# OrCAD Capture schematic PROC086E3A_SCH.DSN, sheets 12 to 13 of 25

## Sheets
12 14. CODEC-B STEREO_MIC 2: size C; title: CODEC-B STEREO MIC 2
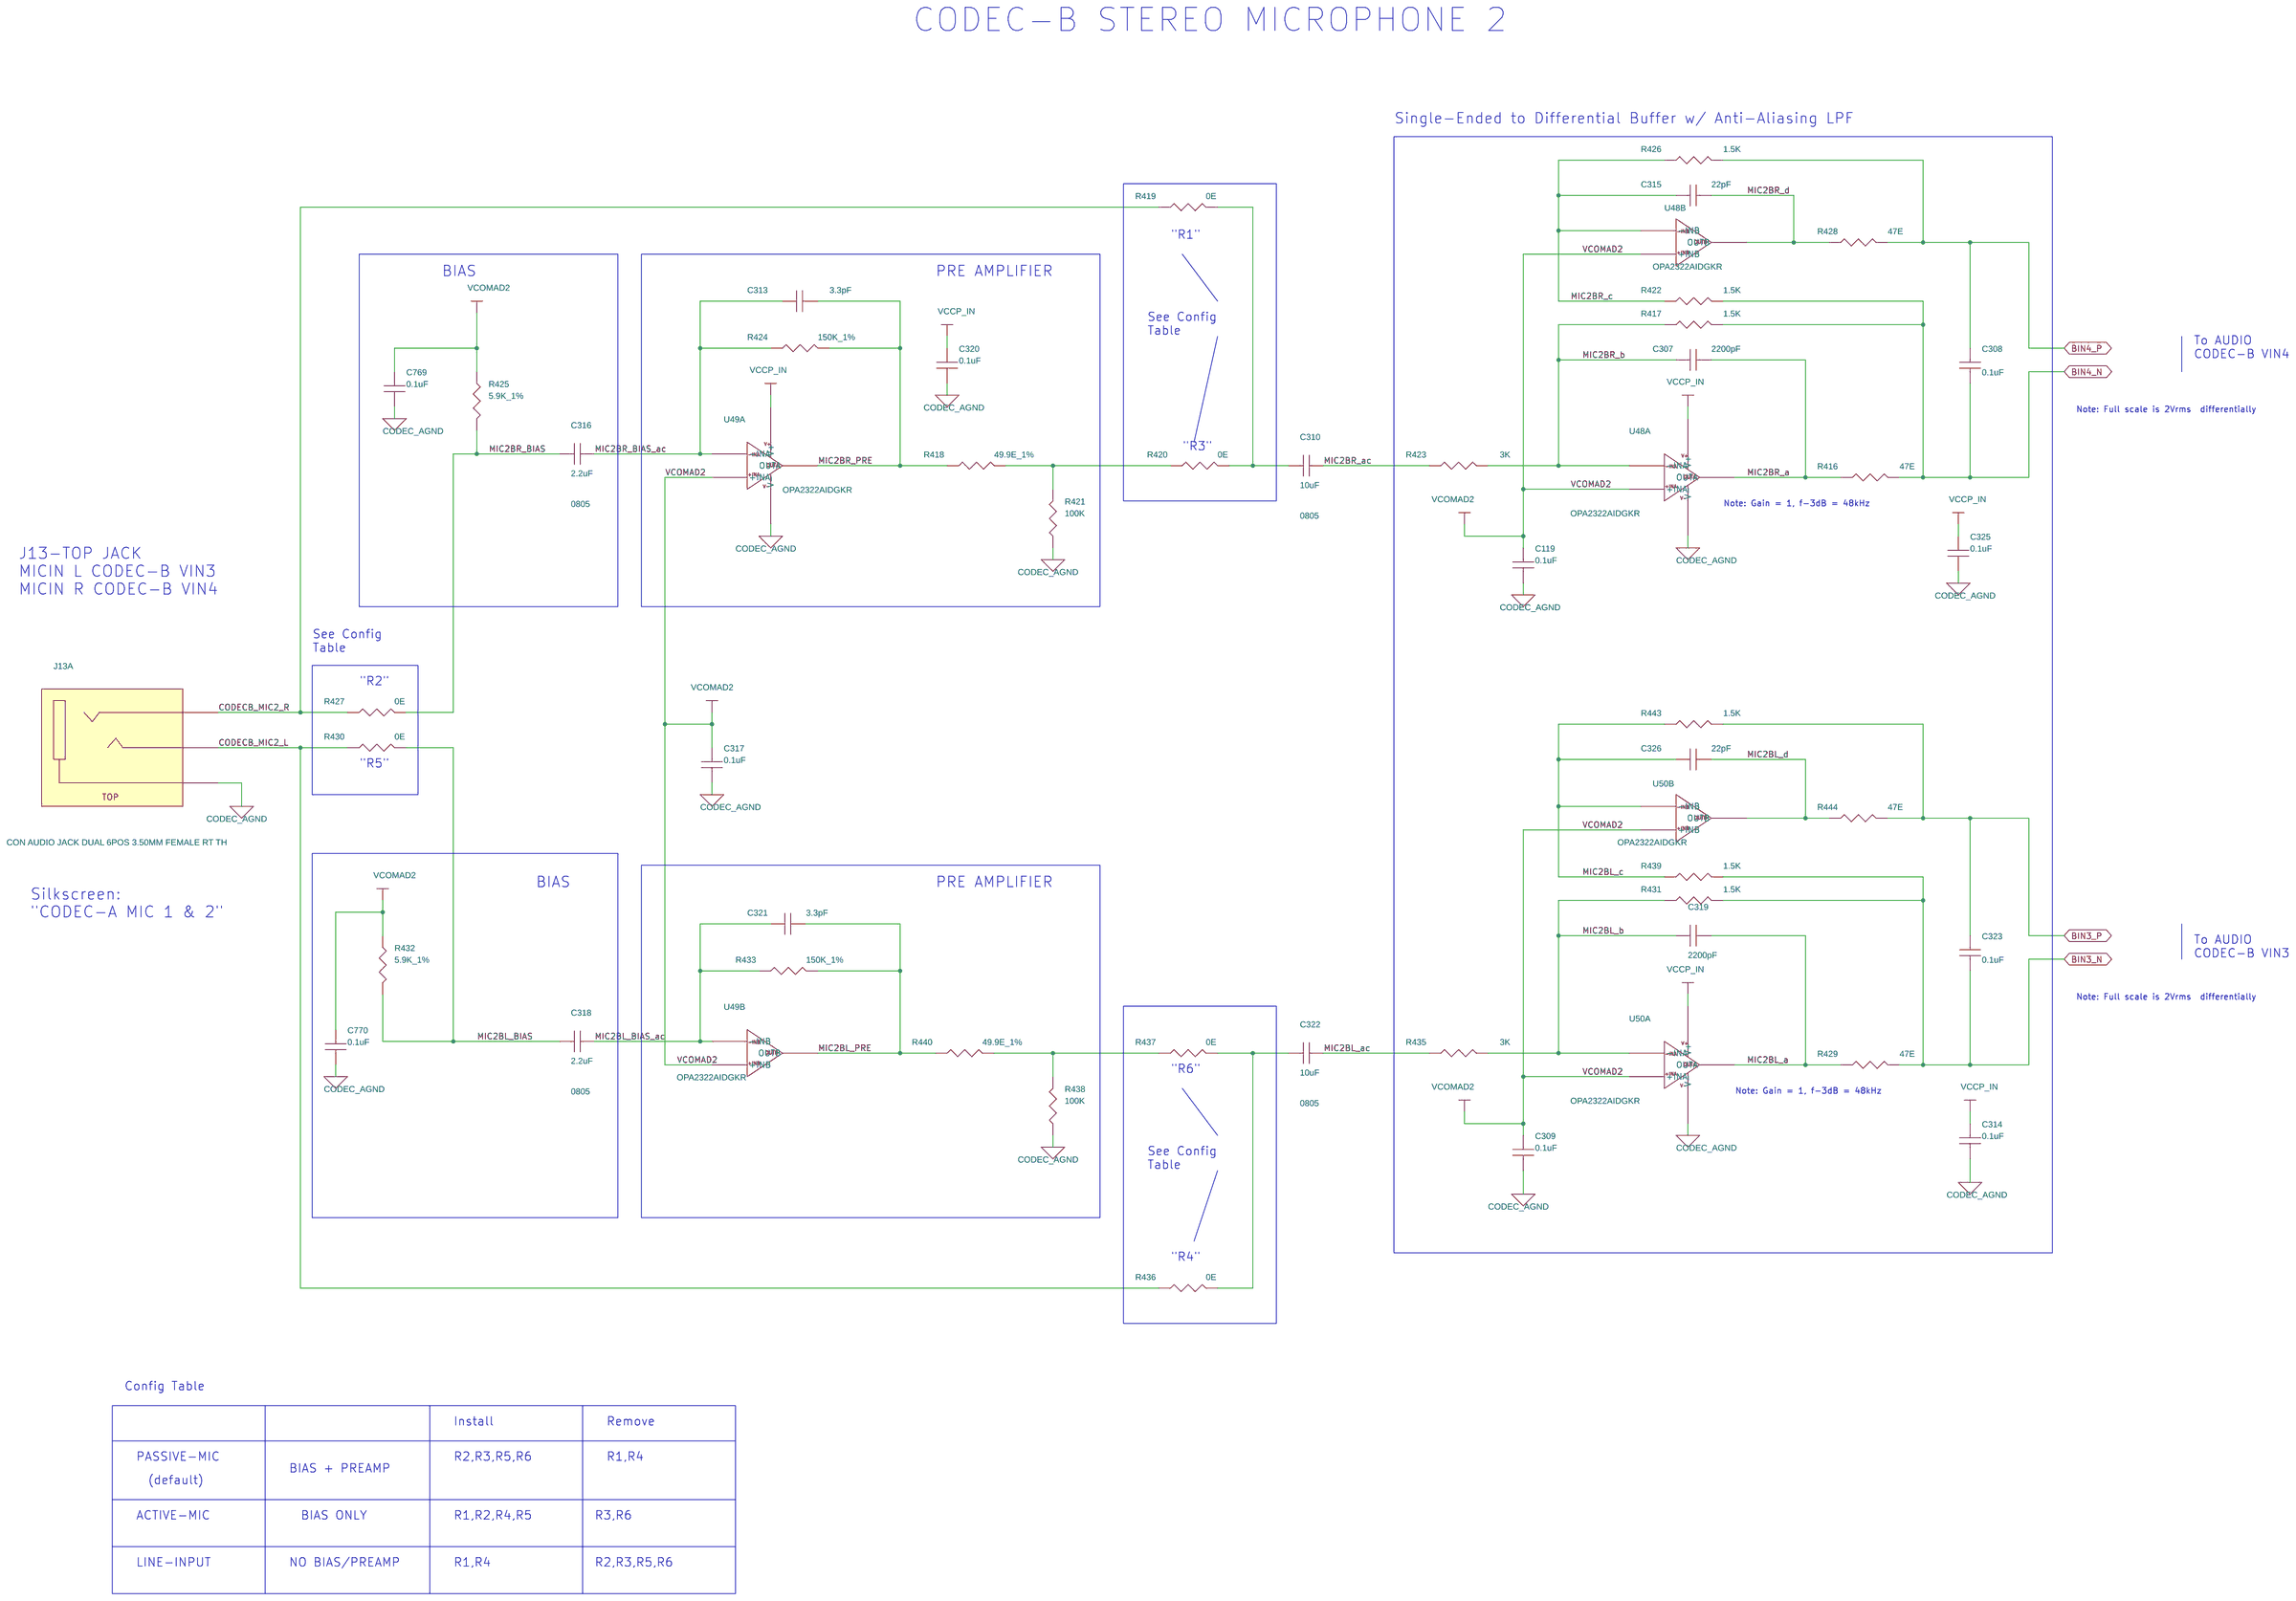
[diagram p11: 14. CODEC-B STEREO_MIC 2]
13 15. CODEC-B STEREO_LINE_OUT: size C; title: CODEC-B STEREO LINE OUT
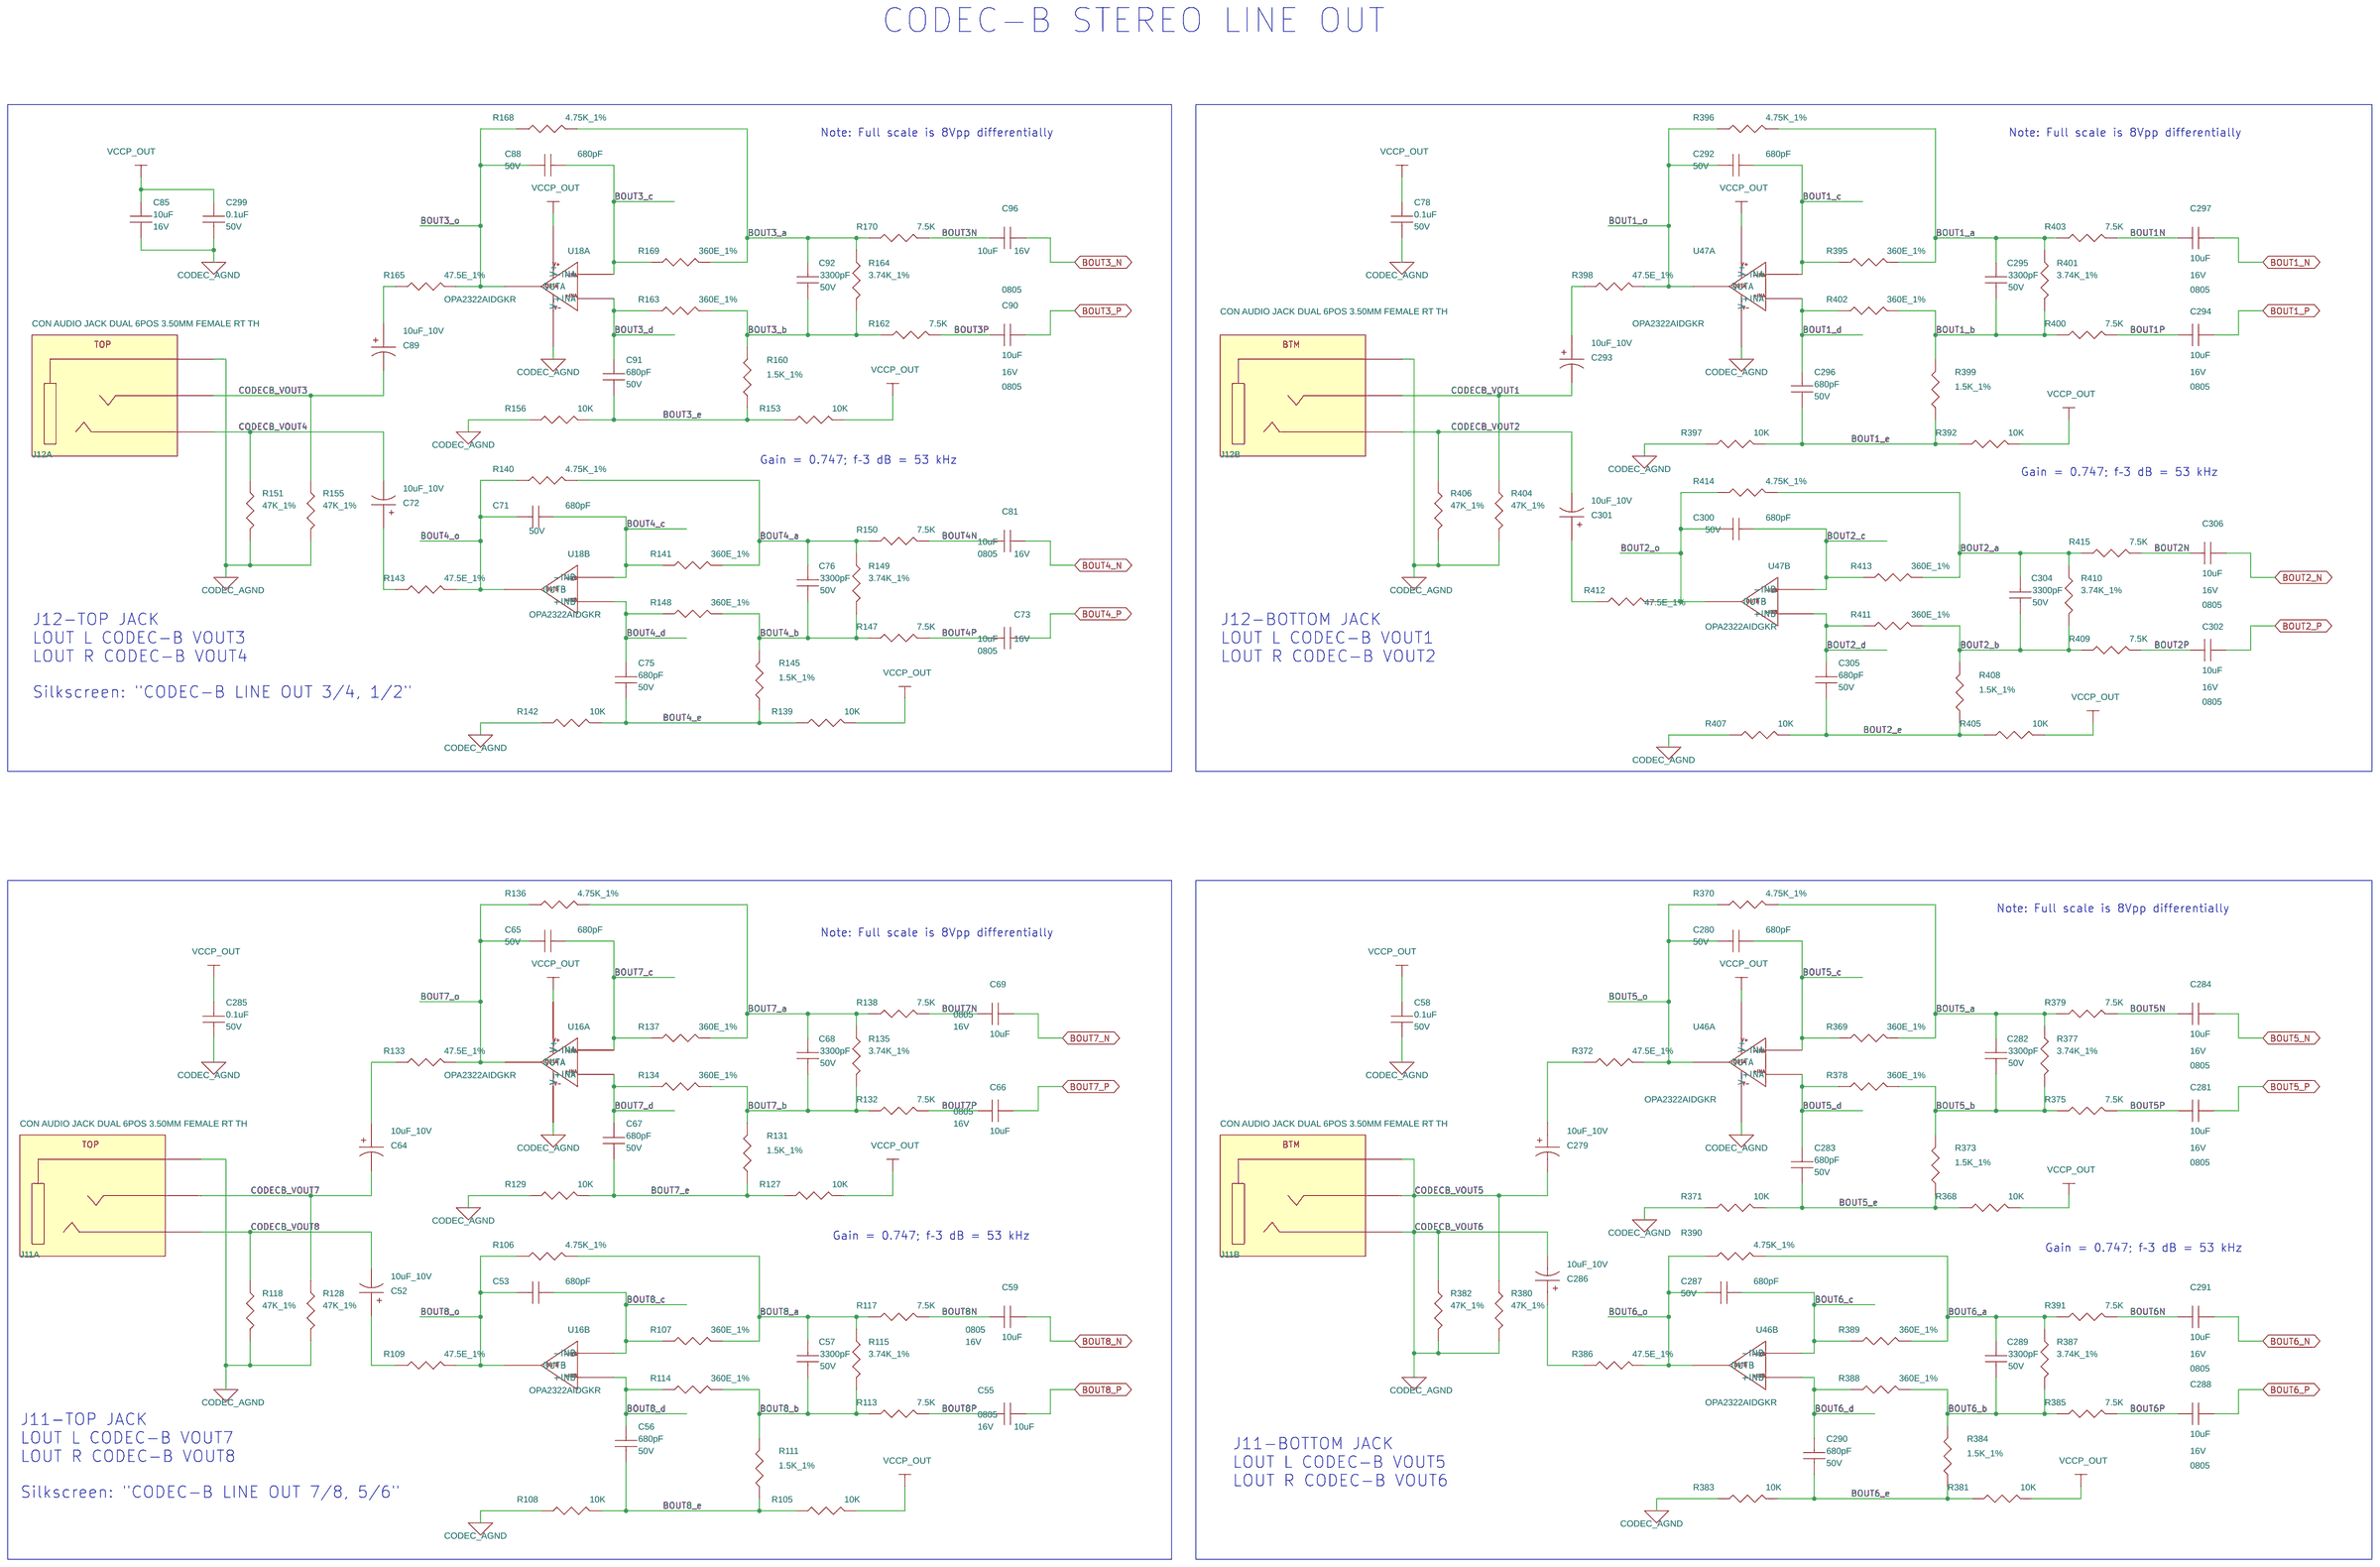
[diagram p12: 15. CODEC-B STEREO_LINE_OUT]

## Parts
sheet 13. CODEC-B STEREO_MIC 1
J13  CON_AUDIOJACK6_STX-4235  [CON_AV6_STX-4235-3-3_S_R_T_26]  (sections A,B)
sheet 14. CODEC-B STEREO_MIC 2
C119  0.1uF  [CAP0402_0-75]
C307  2200pF  [CAP0402_0-75]
C308  0.1uF  [CAP0402_0-75]
C309  0.1uF  [CAP0402_0-75]
C310  10uF  [CAP0805_1-5]
C313  3.3pF  [CAP0402_0-75]
C314  0.1uF  [CAP0402_0-75]
C315  22pF  [CAP0402_0-75]
C316  2.2uF  [CAP0805_1-5]
C317  0.1uF  [CAP0402_0-75]
C318  2.2uF  [CAP0805_1-5]
C319  2200pF  [CAP0402_0-75]
C320  0.1uF  [CAP0402_0-75]
C321  3.3pF  [CAP0402_0-75]
C322  10uF  [CAP0805_1-5]
C323  0.1uF  [CAP0402_0-75]
C325  0.1uF  [CAP0402_0-75]
C326  22pF  [CAP0402_0-75]
C769  0.1uF  [CAP0402_0-75]
C770  0.1uF  [CAP0402_0-75]
R416  47E  [RES0402_0-5]
R417  1.5K  [RES0402_0-5]
R418  49.9E_1%  [RES0402_0-5]
R419  0E  [RES0402_0-5]
R420  0E  [RES0402_0-5]
R421  100K  [RES0402_0-5]
R422  1.5K  [RES0402_0-5]
R423  3K  [RES0402_0-5]
R424  150K_1%  [RES0402_0-5]
R425  5.9K_1%  [RES0402_0-5]
R426  1.5K  [RES0402_0-5]
R427  0E  [RES0402_0-5]
R428  47E  [RES0402_0-5]
R429  47E  [RES0402_0-5]
R430  0E  [RES0402_0-5]
R431  1.5K  [RES0402_0-5]
R432  5.9K_1%  [RES0402_0-5]
R433  150K_1%  [RES0402_0-5]
R435  3K  [RES0402_0-5]
R436  0E  [RES0402_0-5]
R437  0E  [RES0402_0-5]
R438  100K  [RES0402_0-5]
R439  1.5K  [RES0402_0-5]
R440  49.9E_1%  [RES0402_0-5]
R443  1.5K  [RES0402_0-5]
R444  47E  [RES0402_0-5]
U48  OPA2322AIDGKR  [VSSOP8_25-59_120X120_1-1]  (sections A,B)
U49  OPA2322AIDGKR  [VSSOP8_25-59_120X120_1-1]  (sections A,B)
U50  OPA2322AIDGKR  [VSSOP8_25-59_120X120_1-1]  (sections A,B)
sheet 15. CODEC-B STEREO_LINE_OUT
C52  10uF_10V  [CAPCT0805H_1]
C53  680pF  [CAP0402_0-75]
C55  10uF  [CAP0805_1-5]
C56  680pF  [CAP0402_0-75]
C57  3300pF  [CAP0402_0-75]
C58  0.1uF  [CAP0402_0-75]
C59  10uF  [CAP0805_1-5]
C64  10uF_10V  [CAPCT0805H_1]
C65  680pF  [CAP0402_0-75]
C66  10uF  [CAP0805_1-5]
C67  680pF  [CAP0402_0-75]
C68  3300pF  [CAP0402_0-75]
C69  10uF  [CAP0805_1-5]
C71  680pF  [CAP0402_0-75]
C72  10uF_10V  [CAPCT0805H_1]
C73  10uF  [CAP0805_1-5]
C75  680pF  [CAP0402_0-75]
C76  3300pF  [CAP0402_0-75]
C78  0.1uF  [CAP0402_0-75]
C81  10uF  [CAP0805_1-5]
C85  10uF  [CAP0603_1]
C88  680pF  [CAP0402_0-75]
C89  10uF_10V  [CAPCT0805H_1]
C90  10uF  [CAP0805_1-5]
C91  680pF  [CAP0402_0-75]
C92  3300pF  [CAP0402_0-75]
C96  10uF  [CAP0805_1-5]
C279  10uF_10V  [CAPCT0805H_1]
C280  680pF  [CAP0402_0-75]
C281  10uF  [CAP0805_1-5]
C282  3300pF  [CAP0402_0-75]
C283  680pF  [CAP0402_0-75]
C284  10uF  [CAP0805_1-5]
C285  0.1uF  [CAP0402_0-75]
C286  10uF_10V  [CAPCT0805H_1]
C287  680pF  [CAP0402_0-75]
C288  10uF  [CAP0805_1-5]
C289  3300pF  [CAP0402_0-75]
C290  680pF  [CAP0402_0-75]
C291  10uF  [CAP0805_1-5]
C292  680pF  [CAP0402_0-75]
C293  10uF_10V  [CAPCT0805H_1]
C294  10uF  [CAP0805_1-5]
C295  3300pF  [CAP0402_0-75]
C296  680pF  [CAP0402_0-75]
C297  10uF  [CAP0805_1-5]
C299  0.1uF  [CAP0402_0-75]
C300  680pF  [CAP0402_0-75]
C301  10uF_10V  [CAPCT0805H_1]
C302  10uF  [CAP0805_1-5]
C304  3300pF  [CAP0402_0-75]
C305  680pF  [CAP0402_0-75]
C306  10uF  [CAP0805_1-5]
J11  CON_AUDIOJACK6_STX-4235  [CON_AV6_STX-4235-3-3_S_R_T_26]  (sections A,B)
J12  CON_AUDIOJACK6_STX-4235  [CON_AV6_STX-4235-3-3_S_R_T_26]  (sections A,B)
R105  10K  [RES0402_0-5]
R106  4.75K_1%  [RES0402_0-5]
R107  360E_1%  [RES0402_0-5]
R108  10K  [RES0402_0-5]
R109  47.5E_1%  [RES0402_0-5]
R111  1.5K_1%  [RES0402_0-5]
R113  7.5K  [RES0402_0-5]
R114  360E_1%  [RES0402_0-5]
R115  3.74K_1%  [RES0402_0-5]
R117  7.5K  [RES0402_0-5]
R118  47K_1%  [RES0402_0-5]
R127  10K  [RES0402_0-5]
R128  47K_1%  [RES0402_0-5]
R129  10K  [RES0402_0-5]
R131  1.5K_1%  [RES0402_0-5]
R132  7.5K  [RES0402_0-5]
R133  47.5E_1%  [RES0402_0-5]
R134  360E_1%  [RES0402_0-5]
R135  3.74K_1%  [RES0402_0-5]
R136  4.75K_1%  [RES0402_0-5]
R137  360E_1%  [RES0402_0-5]
R138  7.5K  [RES0402_0-5]
R139  10K  [RES0402_0-5]
R140  4.75K_1%  [RES0402_0-5]
R141  360E_1%  [RES0402_0-5]
R142  10K  [RES0402_0-5]
R143  47.5E_1%  [RES0402_0-5]
R145  1.5K_1%  [RES0402_0-5]
R147  7.5K  [RES0402_0-5]
R148  360E_1%  [RES0402_0-5]
R149  3.74K_1%  [RES0402_0-5]
R150  7.5K  [RES0402_0-5]
R151  47K_1%  [RES0402_0-5]
R153  10K  [RES0402_0-5]
R155  47K_1%  [RES0402_0-5]
R156  10K  [RES0402_0-5]
R160  1.5K_1%  [RES0402_0-5]
R162  7.5K  [RES0402_0-5]
R163  360E_1%  [RES0402_0-5]
R164  3.74K_1%  [RES0402_0-5]
R165  47.5E_1%  [RES0402_0-5]
R168  4.75K_1%  [RES0402_0-5]
R169  360E_1%  [RES0402_0-5]
R170  7.5K  [RES0402_0-5]
R368  10K  [RES0402_0-5]
R369  360E_1%  [RES0402_0-5]
R370  4.75K_1%  [RES0402_0-5]
R371  10K  [RES0402_0-5]
R372  47.5E_1%  [RES0402_0-5]
R373  1.5K_1%  [RES0402_0-5]
R375  7.5K  [RES0402_0-5]
R377  3.74K_1%  [RES0402_0-5]
R378  360E_1%  [RES0402_0-5]
R379  7.5K  [RES0402_0-5]
R380  47K_1%  [RES0402_0-5]
R381  10K  [RES0402_0-5]
R382  47K_1%  [RES0402_0-5]
R383  10K  [RES0402_0-5]
R384  1.5K_1%  [RES0402_0-5]
R385  7.5K  [RES0402_0-5]
R386  47.5E_1%  [RES0402_0-5]
R387  3.74K_1%  [RES0402_0-5]
R388  360E_1%  [RES0402_0-5]
R389  360E_1%  [RES0402_0-5]
R390  4.75K_1%  [RES0402_0-5]
R391  7.5K  [RES0402_0-5]
R392  10K  [RES0402_0-5]
R395  360E_1%  [RES0402_0-5]
R396  4.75K_1%  [RES0402_0-5]
R397  10K  [RES0402_0-5]
R398  47.5E_1%  [RES0402_0-5]
R399  1.5K_1%  [RES0402_0-5]
R400  7.5K  [RES0402_0-5]
R401  3.74K_1%  [RES0402_0-5]
R402  360E_1%  [RES0402_0-5]
R403  7.5K  [RES0402_0-5]
R404  47K_1%  [RES0402_0-5]
R405  10K  [RES0402_0-5]
R406  47K_1%  [RES0402_0-5]
R407  10K  [RES0402_0-5]
R408  1.5K_1%  [RES0402_0-5]
R409  7.5K  [RES0402_0-5]
R410  3.74K_1%  [RES0402_0-5]
R411  360E_1%  [RES0402_0-5]
R412  47.5E_1%  [RES0402_0-5]
R413  360E_1%  [RES0402_0-5]
R414  4.75K_1%  [RES0402_0-5]
R415  7.5K  [RES0402_0-5]
U16  OPA2322AIDGKR  [VSSOP8_25-59_120X120_1-1]  (sections A,B)
U18  OPA2322AIDGKR  [VSSOP8_25-59_120X120_1-1]  (sections A,B)
U46  OPA2322AIDGKR  [VSSOP8_25-59_120X120_1-1]  (sections A,B)
U47  OPA2322AIDGKR  [VSSOP8_25-59_120X120_1-1]  (sections A,B)

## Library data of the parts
J11-J13 = CON_AUDIOJACK6_STX-4235-3_3: CON AUDIO JACK DUAL 6POS 3.50MM FEMALE RT TH; Chkd/date: MANIRAJA/090818; Crtd /date: ALVY/080818; Custom_Duty: 24%; Customs_HS_Code: 85369090; Distributor_name: MOUSER; Distributor_part_number: 806-STX-4235-3/3-N; Footprint Path: Y:\MIS_DATABASE\Library\ALTIUM_TOOL\PCB_FOOTPRINTS\Altium_Footprint_Lib.PcbLib; Height: 26.00MM; Library Path: Y:\MIS_DATABASE\Library\ALTIUM_TOOL\SCHEMATICS_PARTS\MS_CONNECTOR_Library.schlib; Library Ref: CON_AUDIOJACK6_STX-4235-3/3; Mfr_name: KYCON; Mfr_part_number: STX-4235-3/3-N; Mistral Part No: 150018080005-R; Package: THRU-HOLE; Part_type: CONNECTOR\JACK; Project: TI_J7ES_EVM_FUSION2_SER_CAP; RoHS: RoHS; Temperature: -25°C+85°C; Tolerance: NA; Voltage: NA; Wattage: NA; Weight: NA; Datasheet: Y:\MIS_DATABASE\DATASHEETS\CONNECTORS\STX-4235-3-3-N.PDF
C58 C78 C119 C285 C299 C308 C309 C314 C317 C320 C323 C325 C769 C770 = CAP: CAP CERAMIC 0.1uF 50V 10% X7R 0402; Chkd/date: VASANTHA/281216; Crtd /date: CHAITHANYA/051011; Custom_Duty: 15%; Customs_HS_Code: 85322990; Distributor_name: DIGIKEY; Distributor_part_number: 445-173610-1-ND; Footprint Path: Y:\MIS_DATABASE\Library\ALTIUM_TOOL\PCB_FOOTPRINTS\Altium_Footprint_Lib.PcbLib; Height: 0.60MM; Library Path: Y:\MIS_DATABASE\Library\ALTIUM_TOOL\SCHEMATICS_PARTS\MS_DISCRETE_Library.schlib; Mfr_name: TDK CORPORATION; Mfr_part_number: C1005X7R1H104K050BE; Mistral Part No: 120011100014-R; Package: 0402; Part_type: CAPACITORS\CERAMIC; Project: VP-4000-BASE-BOARD; RoHS: RoHS; Temperature: -55°C+125°C; Tolerance: 10%; Voltage: 50V; Wattage: NA; Weight: 0.65mg; Datasheet: Y:\MIS_DATABASE\DATASHEETS\CAPACITORS\TDK_C-SER_FEB19.PDF
C307 C319 = CAP: CAP CERAMIC 2200pF 50V 5% X7R 0402; Chkd/date: MANIRAJA/030619; Crtd /date: ALVY/310519; Custom_Duty: 15%; Customs_HS_Code: 85322990; Distributor_name: DIGIKEY; Distributor_part_number: 1276-1532-1-ND; Footprint Path: Y:\MIS_DATABASE\Library\ALTIUM_TOOL\PCB_FOOTPRINTS\Altium_Footprint_Lib.PcbLib; Height: 0.55MM; Library Path: Y:\MIS_DATABASE\Library\ALTIUM_TOOL\SCHEMATICS_PARTS\MS_DISCRETE_Library.schlib; Mfr_name: SAMSUNG; Mfr_part_number: CL05B222JB5NNNC; Mistral Part No: 120013090018-R; Package: 0402; Part_type: CAPACITORS\CERAMIC; Project: J7ES_SOM_DUAL-LEO_PMIC; RoHS: RoHS; Temperature: -55°C+125°C; Tolerance: 5%; Voltage: 50V; Wattage: NA; Weight: NA; Datasheet: Y:\MIS_DATABASE\DATASHEETS\CAPACITORS\CL05B222JB5NNNC.PDF
C55 C59 C66 C69 C73 C81 C90 C96 C281 C284 C288 C291 C294 C297 C302 C306 C310 C322 = CAP: CAP CERAMIC 10uF 16V 10% X5R 0805; Chkd/date: SHREESHAIL/220506; Crtd /date: MAZHAR/150506; Custom_Duty: 15%; Customs_HS_Code: 85322990; Distributor_name: DIGIKEY; Distributor_part_number: 490-3886-1-ND; Footprint Path: Y:\MIS_DATABASE\Library\ALTIUM_TOOL\PCB_FOOTPRINTS\Altium_Footprint_Lib.PcbLib; Height: 1.35MM; Library Path: Y:\MIS_DATABASE\Library\ALTIUM_TOOL\SCHEMATICS_PARTS\MS_DISCRETE_Library.schlib; Mfr_name: MURATA; Mfr_part_number: GRM21BR61C106KE15L; Mistral Part No: 120009030205-R; Package: 0805; Part_type: CAPACITORS\CERAMIC; Project: VOCERA; RoHS: RoHS; Temperature: -55°C+85°C; Tolerance: 10%; Voltage: 16V; Wattage: NA; Weight: 9.5mg; Datasheet: Y:\MIS_DATABASE\DATASHEETS\CAPACITORS\MURATA-GXX-SER_NOV17.PDF
C313 C321 = CAP: CAP CERAMIC 3.3pF 50V 0.25pF C0G(NP0) 0402; Chkd/date: SHREESHAIL/281105; Crtd /date: MAZHAR/211005; Custom_Duty: 15%; Customs_HS_Code: 85322990; Distributor_name: DIGIKEY; Distributor_part_number: 478-1064-1-ND; Footprint Path: Y:\MIS_DATABASE\Library\ALTIUM_TOOL\PCB_FOOTPRINTS\Altium_Footprint_Lib.PcbLib; Height: 0.56MM; Library Path: Y:\MIS_DATABASE\Library\ALTIUM_TOOL\SCHEMATICS_PARTS\MS_DISCRETE_Library.schlib; Mfr_name: AVX CORPORATION; Mfr_part_number: 04025A3R3CAT2A; Mistral Part No: 120009030354-R; Package: 0402; Part_type: CAPACITORS\CERAMIC; Project: EPDA_CORE; RoHS: RoHS; Temperature: -55°C+125°C; Tolerance: 0.25pF%; Voltage: 50V; Wattage: NA; Weight: 0.65mg; Datasheet: Y:\MIS_DATABASE\DATASHEETS\CAPACITORS\AVX_MLC.PDF
C315 C326 = CAP: CAP CERAMIC 22pF 50V 5% C0G(NP0) 0402; Chkd/date: MANIRAJA/060619; Crtd /date: MANIRAJA/060619; Custom_Duty: 15%; Customs_HS_Code: 85322990; Distributor_name: DIGIKEY; Distributor_part_number: 1276-1116-1-ND; Footprint Path: Y:\MIS_DATABASE\Library\ALTIUM_TOOL\PCB_FOOTPRINTS\Altium_Footprint_Lib.PcbLib; Height: 0.55MM; Library Path: Y:\MIS_DATABASE\Library\ALTIUM_TOOL\SCHEMATICS_PARTS\MS_DISCRETE_Library.schlib; Mfr_name: SAMSUNG; Mfr_part_number: CL05C220JB5NNNC; Mistral Part No: 120014100023-R; Package: 0402; Part_type: CAPACITORS\CERAMIC; Project: J7ES_SOM_DUAL-LEO_PMIC; RoHS: RoHS; Temperature: -55°C+125°C; Tolerance: 5%; Voltage: 50V; Wattage: NA; Weight: 0.65mg; Datasheet: Y:\MIS_DATABASE\DATASHEETS\CAPACITORS\CL05C220JB5NNNC.PDF
C316 C318 = CAP: CAP CERAMIC 2.2uF 50V 20% X7R 0805; Chkd/date: MANIRAJA/241018; Crtd /date: ALVY/241018; Custom_Duty: 15%; Customs_HS_Code: 85322990; Distributor_name: DIGIKEY; Distributor_part_number: 445-172488-1-ND; Footprint Path: Y:\MIS_DATABASE\Library\ALTIUM_TOOL\PCB_FOOTPRINTS\Altium_Footprint_Lib.PcbLib; Height: 1.50MM; Library Path: Y:\MIS_DATABASE\Library\ALTIUM_TOOL\SCHEMATICS_PARTS\MS_DISCRETE_Library.schlib; Mfr_name: TDK CORPORATION; Mfr_part_number: C2012X7R1H225M125AE; Mistral Part No: 120018100054-R; Package: 0805; Part_type: CAPACITORS\CERAMIC; Project: TI_J7ES_EVM_CP; RoHS: RoHS; Temperature: -55°C+125°C; Tolerance: 20%; Voltage: 50V; Wattage: NA; Weight: 5.5mg; Datasheet: Y:\MIS_DATABASE\DATASHEETS\CAPACITORS\TDK-CAP-E-SER.PDF
R416 R428 R429 R444 = RESISTOR: RES 47E 1/16W 5% 0402; Chkd/date: MANIRAJA/250319; Crtd /date: MANIRAJA/250319; Custom_Duty: 15%; Customs_HS_Code: 85332119; Distributor_name: DIGIKEY; Distributor_part_number: 311-47JRCT-ND; Footprint Path: Y:\MIS_DATABASE\Library\ALTIUM_TOOL\PCB_FOOTPRINTS\Altium_Footprint_Lib.PcbLib; Height: 0.40MM; Library Path: Y:\MIS_DATABASE\Library\ALTIUM_TOOL\SCHEMATICS_PARTS\MS_DISCRETE_Library.schlib; Mfr_name: YAGEO AMERICA; Mfr_part_number: RC0402JR-0747RL; Mistral Part No: 110019040221-R; Package: 0402; Part_type: RESISTORS\FIXED; Project: POWERBOX; RoHS: RoHS; Temperature: -55°C+155°C; Tolerance: 5%; Voltage: NA; Wattage: 1/16W; Weight: 0.65mg; Datasheet: Y:\MIS_DATABASE\DATASHEETS\RESISTORS\RCXXXXL-SER_MAR18.PDF
R417 R422 R426 R431 R439 R443 = RESISTOR: RES 1.5K 1/16W 5% 0402; Chkd/date: MANIRAJA/310718; Crtd /date: BAVISH/021210; Custom_Duty: 15%; Customs_HS_Code: 85332119; Distributor_name: DIGIKEY; Distributor_part_number: 311-1.5KJRCT-ND; Footprint Path: Y:\MIS_DATABASE\Library\ALTIUM_TOOL\PCB_FOOTPRINTS\Altium_Footprint_Lib.PcbLib; Height: 0.40MM; Library Path: Y:\MIS_DATABASE\Library\ALTIUM_TOOL\SCHEMATICS_PARTS\MS_DISCRETE_Library.schlib; Mfr_name: YAGEO AMERICA; Mfr_part_number: RC0402JR-071K5L; Mistral Part No: 110010120012-R; Package: 0402; Part_type: RESISTORS\FIXED; Project: TE4; RoHS: RoHS; Temperature: -55°C+155°C; Tolerance: 5%; Voltage: NA; Wattage: 1/16W; Weight: 0.65mg; Datasheet: Y:\MIS_DATABASE\DATASHEETS\RESISTORS\RCXXXXL-SER_MAR18.PDF
R418 R440 = RESISTOR: RES 49.9E 1/10W 1% 0402; Chkd/date: VASANTHA/201216; Crtd /date: MAZHAR/201005; Custom_Duty: 15%; Customs_HS_Code: 85332119; Distributor_name: DIGIKEY; Distributor_part_number: P49.9LCT-ND; Footprint Path: Y:\MIS_DATABASE\Library\ALTIUM_TOOL\PCB_FOOTPRINTS\Altium_Footprint_Lib.PcbLib; Height: 0.40MM; Library Path: Y:\MIS_DATABASE\Library\ALTIUM_TOOL\SCHEMATICS_PARTS\MS_DISCRETE_Library.schlib; Mfr_name: PANASONIC-ECG; Mfr_part_number: ERJ-2RKF49R9X; Mistral Part No: 110009030897-R; Package: 0402; Part_type: RESISTORS\FIXED; Project: RED EYE; RoHS: RoHS; Temperature: -55°C+155°C; Tolerance: 1%; Voltage: NA; Wattage: 1/10W; Weight: 0.8mg; Datasheet: Y:\MIS_DATABASE\DATASHEETS\RESISTORS\PAN-ERJSER_NOV17.PDF
R419 R436 = RESISTOR: RES 0E 1/10W JUMPER 0402; Assembly_Instruction: DNI; Chkd/date: VASANTHA/061216; Crtd /date: NAVEED/201014; Custom_Duty: 15%; Customs_HS_Code: 85332119; Distributor_name: DIGIKEY; Distributor_part_number: P0.0JCT-ND; Footprint Path: Y:\MIS_DATABASE\Library\ALTIUM_TOOL\PCB_FOOTPRINTS\Altium_Footprint_Lib.PcbLib; Height: 0.40MM; IBISSP_MODLES: VALUE REPEATING 2 TIME; Library Path: Y:\MIS_DATABASE\Library\ALTIUM_TOOL\SCHEMATICS_PARTS\MS_DISCRETE_Library.schlib; Mfr_name: PANASONIC-ECG; Mfr_part_number: ERJ-2GE0R00X; Mistral Part No: 110018030052-R; Package: 0402; Part_type: RESISTORS\FIXED; Project: AEGIS POM; RoHS: RoHS; Temperature: -55°C+155°C; Tolerance: NA; Voltage: NA; Wattage: 1/10W; Weight: 0.8mg; Datasheet: Y:\MIS_DATABASE\DATASHEETS\RESISTORS\PAN-ERJSER_NOV17.PDF
R420 R427 R430 R437 = RESISTOR: RES 0E 1/10W JUMPER 0402; Chkd/date: VASANTHA/061216; Crtd /date: NAVEED/201014; Custom_Duty: 15%; Customs_HS_Code: 85332119; Distributor_name: DIGIKEY; Distributor_part_number: P0.0JCT-ND; Footprint Path: Y:\MIS_DATABASE\Library\ALTIUM_TOOL\PCB_FOOTPRINTS\Altium_Footprint_Lib.PcbLib; Height: 0.40MM; IBISSP_MODLES: VALUE REPEATING 2 TIME; Library Path: Y:\MIS_DATABASE\Library\ALTIUM_TOOL\SCHEMATICS_PARTS\MS_DISCRETE_Library.schlib; Mfr_name: PANASONIC-ECG; Mfr_part_number: ERJ-2GE0R00X; Mistral Part No: 110018030052-R; Package: 0402; Part_type: RESISTORS\FIXED; Project: AEGIS POM; RoHS: RoHS; Temperature: -55°C+155°C; Tolerance: NA; Voltage: NA; Wattage: 1/10W; Weight: 0.8mg; Datasheet: Y:\MIS_DATABASE\DATASHEETS\RESISTORS\PAN-ERJSER_NOV17.PDF
R421 R438 = RESISTOR: RES 100K 1/16W 5% 0402; Assembly_Instruction: DNI; Chkd/date: VASANTHA/130516; Crtd /date: VASANTHA/130516; Custom_Duty: 15%; Customs_HS_Code: 85332119; Distributor_name: DIGIKEY; Distributor_part_number: A121521CT-ND; Footprint Path: Y:\MIS_DATABASE\Library\ALTIUM_TOOL\PCB_FOOTPRINTS\Altium_Footprint_Lib.PcbLib; Height: 0.40MM; Library Path: Y:\MIS_DATABASE\Library\ALTIUM_TOOL\SCHEMATICS_PARTS\MS_DISCRETE_Library.schlib; Mfr_name: TE CONNECTIVITY; Mfr_part_number: CRG0402J100K/10; Mistral Part No: 110019040062-R; Package: 0402; Part_type: RESISTORS\FIXED; Project: TMDXCSK368; RoHS: RoHS; Temperature: -55°C+125°C; Tolerance: 5%; Voltage: NA; Wattage: 1/16W; Weight: 0.65mg; Datasheet: Y:\MIS_DATABASE\DATASHEETS\RESISTORS\CRG-SERIES.PDF
R423 R435 = RESISTOR: RES 3K 1/10W 5% 0402; Chkd/date: MAZHAR/150709; Crtd /date: MAZHAR/110907; Custom_Duty: 15%; Customs_HS_Code: 85332119; Distributor_name: DIGIKEY; Distributor_part_number: P3.0KJCT-ND; Footprint Path: Y:\MIS_DATABASE\Library\ALTIUM_TOOL\PCB_FOOTPRINTS\Altium_Footprint_Lib.PcbLib; Height: 0.40MM; Library Path: Y:\MIS_DATABASE\Library\ALTIUM_TOOL\SCHEMATICS_PARTS\MS_DISCRETE_Library.schlib; Mfr_name: PANASONIC-ECG; Mfr_part_number: ERJ-2GEJ302X; Mistral Part No: 110009030764-R; Package: 0402; Part_type: RESISTORS\FIXED; Project: TELEMETRY ENCODER; RoHS: RoHS; Temperature: -55°C+155°C; Tolerance: 5%; Voltage: NA; Wattage: 1/10W; Weight: 0.8mg; Datasheet: Y:\MIS_DATABASE\DATASHEETS\RESISTORS\PAN-ERJSER_NOV17.PDF
R424 R433 = RESISTOR: RES 150K 1/10W 1% 0402; Chkd/date: SHREESHAIL/200906; Crtd /date: MAZHAR/190906; Custom_Duty: 15%; Customs_HS_Code: 85332119; Distributor_name: DIGIKEY; Distributor_part_number: P150KLCT-ND; Footprint Path: Y:\MIS_DATABASE\Library\ALTIUM_TOOL\PCB_FOOTPRINTS\Altium_Footprint_Lib.PcbLib; Height: 0.40MM; Library Path: Y:\MIS_DATABASE\Library\ALTIUM_TOOL\SCHEMATICS_PARTS\MS_DISCRETE_Library.schlib; Mfr_name: PANASONIC-ECG; Mfr_part_number: ERJ-2RKF1503X; Mistral Part No: 110009030336-R; Package: 0402; Part_type: RESISTORS\FIXED; Project: SM2_AFE; RoHS: RoHS; Temperature: -55°C+155°C; Tolerance: 1%; Voltage: NA; Wattage: 1/10W; Weight: 0.8mg; Datasheet: Y:\MIS_DATABASE\DATASHEETS\RESISTORS\PAN-ERJSER_NOV17.PDF
R425 R432 = RESISTOR: RES 5.9K 1/10W 1% 0402; Chkd/date: MAZHAR/251110; Crtd /date: BAVISH/251110; Custom_Duty: 15%; Customs_HS_Code: 85332119; Distributor_name: DIGIKEY; Distributor_part_number: P5.90KLCT-ND; Footprint Path: Y:\MIS_DATABASE\Library\ALTIUM_TOOL\PCB_FOOTPRINTS\Altium_Footprint_Lib.PcbLib; Height: 0.40MM; Library Path: Y:\MIS_DATABASE\Library\ALTIUM_TOOL\SCHEMATICS_PARTS\MS_DISCRETE_Library.schlib; Mfr_name: PANASONIC-ECG; Mfr_part_number: ERJ-2RKF5901X; Mistral Part No: 110010110029-R; Package: 0402; Part_type: RESISTORS\FIXED; Project: CENTAURUS; RoHS: RoHS; Temperature: -55°C+155°C; Tolerance: 1%; Voltage: NA; Wattage: 1/10W; Weight: 0.8mg; Datasheet: Y:\MIS_DATABASE\DATASHEETS\RESISTORS\PAN-ERJSER_NOV17.PDF
U16 U18 U46-U50 = OPA2350UA_SOIC8: IC 20MHz 1.8V LOW NOISE RRI/O CMOS OPAMP VSSOP8; Chkd/date: MANIRAJA/161018; Crtd /date: ALVY/161018; Custom_Duty: 15%; Customs_HS_Code: 85423100; Distributor_name: DIGIKEY; Distributor_part_number: 296-41349-1-ND; Footprint Path: Y:\MIS_DATABASE\Library\ALTIUM_TOOL\PCB_FOOTPRINTS\Altium_Footprint_Lib.PcbLib; Height: 1.10MM; Library Path: Y:\MIS_DATABASE\Library\ALTIUM_TOOL\SCHEMATICS_PARTS\MS_OPAMP_Library.schlib; Mfr_name: TEXAS INSTRUMENTS; Mistral Part No: 140118100019-R; Package: VSSOP8; Part_type: ICS\ANALOG\OPAMP; Project: TI_J7ES_EVM_CP; RoHS: RoHS; Temperature: -40°C+125°C; Tolerance: NA; Voltage: NA; Wattage: NA; Weight: 26.5mg; Datasheet: Y:\MIS_DATABASE\DATASHEETS\ICS\OPAMP\OPA2322XX.PDF
C52 C64 C72 C89 C279 C286 C293 C301 = CAP_POL: CAP TANTALUM 10uF 10V 20% ESR 5E H0805; Chkd/date: MANIRAJA/091018; Crtd /date: ALVY/091018; Custom_Duty: 15%; Customs_HS_Code: 85322990; Distributor_name: DIGIKEY; Distributor_part_number: 478-11046-1-ND; Footprint Path: Y:\MIS_DATABASE\Library\ALTIUM_TOOL\PCB_FOOTPRINTS\Altium_Footprint_Lib.PcbLib; Height: 1.00MM; Library Path: Y:\MIS_DATABASE\Library\ALTIUM_TOOL\SCHEMATICS_PARTS\MS_DISCRETE_Library.schlib; Mfr_name: AVX CORPORATION; Mfr_part_number: TACH106M010XTA; Mistral Part No: 120018100018-R; Package: H0805; Part_type: CAPACITORS\TANTALUM; Project: TI_J7ES_EVM_CP; RoHS: RoHS; Temperature: -55°C+125°C; Tolerance: 20%; Voltage: 10V; Wattage: NA; Weight: 5.5mg; Datasheet: Y:\MIS_DATABASE\DATASHEETS\CAPACITORS\AVX-TAC-APR18.PDF
C53 C56 C65 C67 C71 C75 C88 C91 C280 C283 C287 C290 C292 C296 C300 C305 = CAP: CAP CERAMIC 680pF 50V 5% X7R 0402; Chkd/date: BAVISH/260911; Crtd /date: CHAITHANYA/260911; Custom_Duty: 15%; Customs_HS_Code: 85322990; Distributor_name: DIGIKEY; Distributor_part_number: 478-5270-1-ND; Footprint Path: Y:\MIS_DATABASE\Library\ALTIUM_TOOL\PCB_FOOTPRINTS\Altium_Footprint_Lib.PcbLib; Height: 0.56MM; Library Path: Y:\MIS_DATABASE\Library\ALTIUM_TOOL\SCHEMATICS_PARTS\MS_DISCRETE_Library.schlib; Mfr_name: AVX CORPORATION; Mfr_part_number: 04025C681JAT2A; Mistral Part No: 120011090031-R; Package: 0402; Part_type: CAPACITORS\CERAMIC; Project: GEMYC; RoHS: RoHS; Temperature: -55°C+125°C; Tolerance: 5%; Voltage: 50V; Wattage: NA; Weight: 0.65mg; Datasheet: Y:\MIS_DATABASE\DATASHEETS\CAPACITORS\AVX_MLC.PDF
C57 C68 C76 C92 C282 C289 C295 C304 = CAP: CAP CERAMIC 3300pF 50V 10% X7R 0402; Chkd/date: MAZHAR/241208; Crtd /date: USMAN/131108; Custom_Duty: 15%; Customs_HS_Code: 85322990; Distributor_name: DIGIKEY; Distributor_part_number: 478-1107-1-ND; Footprint Path: Y:\MIS_DATABASE\Library\ALTIUM_TOOL\PCB_FOOTPRINTS\Altium_Footprint_Lib.PcbLib; Height: 0.56MM; Library Path: Y:\MIS_DATABASE\Library\ALTIUM_TOOL\SCHEMATICS_PARTS\MS_DISCRETE_Library.schlib; Mfr_name: AVX CORPORATION; Mfr_part_number: 04025C332KAT2A; Mistral Part No: 120009030367-R; Package: 0402; Part_type: CAPACITORS\CERAMIC; Project: P2ER6DB; RoHS: RoHS; Temperature: -55°C+125°C; Tolerance: 10%; Voltage: 50V; Wattage: NA; Weight: 0.65mg; Datasheet: Y:\MIS_DATABASE\DATASHEETS\CAPACITORS\AVX_MLC.PDF
C85 = CAP: CAP CERAMIC 10uF 16V 20% X6S 0603; Chkd/date: VASANTHA/170117; Crtd /date: VASANTHA/170117; Custom_Duty: 15%; Customs_HS_Code: 85322990; Distributor_name: DIGIKEY; Distributor_part_number: 490-7198-1-ND; Footprint Path: Y:\MIS_DATABASE\Library\ALTIUM_TOOL\PCB_FOOTPRINTS\Altium_Footprint_Lib.PcbLib; Height: 0.90MM; Library Path: Y:\MIS_DATABASE\Library\ALTIUM_TOOL\SCHEMATICS_PARTS\MS_DISCRETE_Library.schlib; Mfr_name: MURATA; Mfr_part_number: GRM188C81C106MA73D; Mistral Part No: 120017010004-R; Package: 0603; Part_type: CAPACITORS\CERAMIC; Project: TRMM_SMART-M_PS; RoHS: RoHS; Temperature: -55°C+105°C; Tolerance: 20%; Voltage: 16V; Wattage: NA; Weight: 6.3mg; Datasheet: Y:\MIS_DATABASE\DATASHEETS\CAPACITORS\MURATA-GXX-SER_NOV17.PDF
R105 R108 R127 R129 R139 R142 R153 R156 R368 R371 R381 R383 R392 R397 R405 R407 = RESISTOR: RES 10K 1/16W 5% 0402; Chkd/date: VASANTHA/061216; Crtd /date: MAZHAR/230805; Custom_Duty: 15%; Customs_HS_Code: 85332119; Distributor_name: DIGIKEY; Distributor_part_number: 311-10KJRCT-ND; Footprint Path: Y:\MIS_DATABASE\Library\ALTIUM_TOOL\PCB_FOOTPRINTS\Altium_Footprint_Lib.PcbLib; Height: 0.40MM; Library Path: Y:\MIS_DATABASE\Library\ALTIUM_TOOL\SCHEMATICS_PARTS\MS_DISCRETE_Library.schlib; Mfr_name: YAGEO AMERICA; Mfr_part_number: RC0402JR-0710KL; Mistral Part No: 110011060021-R; Package: 0402; Part_type: RESISTORS\FIXED; Project: HSE; RoHS: RoHS; Temperature: -55°C+155°C; Tolerance: 5%; Voltage: NA; Wattage: 1/16W; Weight: 0.65mg; Datasheet: Y:\MIS_DATABASE\DATASHEETS\RESISTORS\RCXXXXL-SER_MAR18.PDF
R106 R136 R140 R168 R370 R390 R396 R414 = RESISTOR: RES 4.75K 1/10W 1% 0402; Chkd/date: BAVISH/100611; Crtd /date: BAVISH/300511; Custom_Duty: 15%; Customs_HS_Code: 85332119; Distributor_name: DIGIKEY; Distributor_part_number: P4.75KLCT-ND; Footprint Path: Y:\MIS_DATABASE\Library\ALTIUM_TOOL\PCB_FOOTPRINTS\Altium_Footprint_Lib.PcbLib; Height: 0.40MM; Library Path: Y:\MIS_DATABASE\Library\ALTIUM_TOOL\SCHEMATICS_PARTS\MS_DISCRETE_Library.schlib; Mfr_name: PANASONIC-ECG; Mfr_part_number: ERJ-2RKF4751X; Mistral Part No: 110011050028-R; Package: 0402; Part_type: RESISTORS\FIXED; Project: AOD_POD-BASECARD; RoHS: RoHS; Temperature: -55°C+155°C; Tolerance: 1%; Voltage: NA; Wattage: 1/10W; Weight: 0.8mg; Datasheet: Y:\MIS_DATABASE\DATASHEETS\RESISTORS\PAN-ERJSER_NOV17.PDF
R107 R114 R134 R137 R141 R148 R163 R169 R369 R378 R388 R389 R395 R402 R411 R413 = RESISTOR: RES 360E 1/16W 1% 0402; Chkd/date: Bavish/240111; Crtd /date: MAZHAR/031210; Custom_Duty: 15%; Customs_HS_Code: 85332119; Distributor_name: DIGIKEY; Distributor_part_number: 541-360LCT-ND; Footprint Path: Y:\MIS_DATABASE\Library\ALTIUM_TOOL\PCB_FOOTPRINTS\Altium_Footprint_Lib.PcbLib; Height: 0.40MM; Library Path: Y:\MIS_DATABASE\Library\ALTIUM_TOOL\SCHEMATICS_PARTS\MS_DISCRETE_Library.schlib; Mfr_name: VISHAY; Mfr_part_number: CRCW0402360RFKED; Mistral Part No: 110010120036-R; Package: 0402; Part_type: RESISTORS\FIXED; Project: CPCI3GADC_CARD; RoHS: RoHS; Temperature: -55°C+155°C; Tolerance: 1%; Voltage: NA; Wattage: 1/16W; Weight: 0.65mg; Datasheet: Y:\MIS_DATABASE\DATASHEETS\RESISTORS\CRCW0603.PDF
R109 R133 R143 R165 R372 R386 R398 R412 = RESISTOR: RES 47.5E 1/10W 1% 0402; Chkd/date: MANIRAJA/060619; Crtd /date: MANIRAJA/060619; Custom_Duty: 15%; Customs_HS_Code: 85332119; Distributor_name: DIGIKEY; Distributor_part_number: P47.5LCT-ND; Footprint Path: Y:\MIS_DATABASE\Library\ALTIUM_TOOL\PCB_FOOTPRINTS\Altium_Footprint_Lib.PcbLib; Height: 0.40MM; Library Path: Y:\MIS_DATABASE\Library\ALTIUM_TOOL\SCHEMATICS_PARTS\MS_DISCRETE_Library.schlib; Mfr_name: PANASONIC-ECG; Mfr_part_number: ERJ-2RKF47R5X; Mistral Part No: 110009030855-R; Package: 0402; Part_type: RESISTORS\FIXED; Project: J7ES_SOM_DUAL-LEO_PMIC; RoHS: RoHS; Temperature: -55°C+155°C; Tolerance: 1%; Voltage: NA; Wattage: 1/10W; Weight: 0.8mg; Datasheet: Y:\MIS_DATABASE\DATASHEETS\RESISTORS\PAN-ERJSER_NOV17.PDF
R111 R131 R145 R160 R373 R384 R399 R408 = RESISTOR: RES 1.5K 1/16W 1% 0402; Chkd/date: VASANTHA/201216; Crtd /date: JEBRAN/250815; Custom_Duty: 15%; Customs_HS_Code: 85332119; Distributor_name: DIGIKEY; Distributor_part_number: 311-1.50KLRCT-ND; Footprint Path: Y:\MIS_DATABASE\Library\ALTIUM_TOOL\PCB_FOOTPRINTS\Altium_Footprint_Lib.PcbLib; Height: 0.40MM; Library Path: Y:\MIS_DATABASE\Library\ALTIUM_TOOL\SCHEMATICS_PARTS\MS_DISCRETE_Library.schlib; Mfr_name: YAGEO AMERICA; Mfr_part_number: RC0402FR-071K5L; Mistral Part No: 110015080041-R; Package: 0402; Part_type: RESISTORS\FIXED; Project: OCTBTS3600; RoHS: RoHS; Temperature: -55°C+155°C; Tolerance: 1%; Voltage: NA; Wattage: 1/16W; Weight: 0.65mg; Datasheet: Y:\MIS_DATABASE\DATASHEETS\RESISTORS\RCXXXXL-SER_MAR18.PDF
R113 R117 R132 R138 R147 R150 R162 R170 R375 R379 R385 R391 R400 R403 R409 R415 = RESISTOR: RES 7.5K 1/16W 5% 0402; Chkd/date: MAZHAR/280108; Crtd /date: USMAN/280108; Custom_Duty: 15%; Customs_HS_Code: 85332119; Distributor_name: DIGIKEY; Distributor_part_number: 541-7.5KJCT-ND; Footprint Path: Y:\MIS_DATABASE\Library\ALTIUM_TOOL\PCB_FOOTPRINTS\Altium_Footprint_Lib.PcbLib; Height: 0.40MM; Library Path: Y:\MIS_DATABASE\Library\ALTIUM_TOOL\SCHEMATICS_PARTS\MS_DISCRETE_Library.schlib; Mfr_name: VISHAY; Mfr_part_number: CRCW04027K50JNED; Mistral Part No: 110009031092-R; Package: 0402; Part_type: RESISTORS\FIXED; Project: TELEMETRY ENCODER; RoHS: RoHS; Temperature: -55°C+155°C; Tolerance: 5%; Voltage: NA; Wattage: 1/16W; Weight: 0.65mg; Datasheet: Y:\MIS_DATABASE\DATASHEETS\RESISTORS\CRCW0603.PDF
R115 R135 R149 R164 R377 R387 R401 R410 = RESISTOR: RES 3.74K 1/10W 1% 0402; Chkd/date: MAZHAR/151208; Crtd /date: USMAN/031208; Custom_Duty: 15%; Customs_HS_Code: 85332119; Distributor_name: DIGIKEY; Distributor_part_number: P3.74KLCT-ND; Footprint Path: Y:\MIS_DATABASE\Library\ALTIUM_TOOL\PCB_FOOTPRINTS\Altium_Footprint_Lib.PcbLib; Height: 0.40MM; Library Path: Y:\MIS_DATABASE\Library\ALTIUM_TOOL\SCHEMATICS_PARTS\MS_DISCRETE_Library.schlib; Mfr_name: PANASONIC-ECG; Mfr_part_number: ERJ-2RKF3741X; Mistral Part No: 110009030640-R; Package: 0402; Part_type: RESISTORS\FIXED; Project: KHAN_HSST; RoHS: RoHS; Temperature: -55°C+155°C; Tolerance: 1%; Voltage: NA; Wattage: 1/10W; Weight: 0.8mg; Datasheet: Y:\MIS_DATABASE\DATASHEETS\RESISTORS\PAN-ERJSER_NOV17.PDF
R118 R128 R151 R155 R380 R382 R404 R406 = RESISTOR: RES 47K 1/16W 1% 0402; Chkd/date: VASANTHA/060117; Crtd /date: MAZHAR/141206; Custom_Duty: 15%; Customs_HS_Code: 85332119; Distributor_name: DIGIKEY; Distributor_part_number: 311-47.0KLRCT-ND; Footprint Path: Y:\MIS_DATABASE\Library\ALTIUM_TOOL\PCB_FOOTPRINTS\Altium_Footprint_Lib.PcbLib; Height: 0.40MM; Library Path: Y:\MIS_DATABASE\Library\ALTIUM_TOOL\SCHEMATICS_PARTS\MS_DISCRETE_Library.schlib; Mfr_name: YAGEO AMERICA; Mfr_part_number: RC0402FR-0747KL; Mistral Part No: 110009030884-R; Package: 0402; Part_type: RESISTORS\FIXED; Project: ADR1B; RoHS: RoHS; Temperature: -55°C+155°C; Tolerance: 1%; Voltage: NA; Wattage: 1/16W; Weight: 0.65mg; Datasheet: Y:\MIS_DATABASE\DATASHEETS\RESISTORS\RCXXXXL-SER_MAR18.PDF

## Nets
DGND: C58.2 C78.2 C85.2 C119.2 C285.2 C299.2 C309.2 C314.2 C317.2 C320.2 C325.2 C769.2 C770.2 J11.1A J11.1B J12.1A J12.1B J13.1A R108.2 R118.2 R128.2 R129.2 R142.2 R151.2 R155.2 R156.2 R371.2 R380.2 R382.2 R383.2 R397.2 R404.2 R406.2 R407.2 R421.1 R438.1 U16.4(V-) U18.4(V-) U46.4(V-) U47.4(V-) U48.4(V-) U49.4(V-) U50.4(V-) ; also on sheet 5 6 7 8 9 10 11 14 15 16 17 18 19 20 21 22 23 25
VCCP_IN: C314.1 C320.1 C325.1 U48.8(V+) U49.8(V+) U50.8(V+) ; also on sheet 6 7 8 10 11 22 23
VCCP_OUT: C58.1 C78.1 C85.1 C285.1 C299.1 R105.1 R127.1 R139.1 R153.1 R368.1 R381.1 R392.1 R405.1 U16.8(V+) U18.8(V+) U46.8(V+) U47.8(V+) ; also on sheet 9
BIN3_N: C323.2 R429.2 R431.2 R439.2 ; also on sheet 22
BIN3_P: C323.1 R443.2 R444.2 ; also on sheet 22
BIN4_N: C308.2 R416.2 R417.2 R422.2 ; also on sheet 22
BIN4_P: C308.1 R426.2 R428.2 ; also on sheet 22
BOUT1_a: C295.1 R395.2 R396.1 R401.1 R403.2
BOUT1_b: C295.2 R399.1 R400.2 R401.2 R402.2
BOUT1_c: C292.1 R395.1 U47.2(-INA)
BOUT1_d: C296.1 R402.1 U47.3(+INA)
BOUT1_e: C296.2 R392.2 R397.1 R399.2
BOUT1_N: C297.2 ; also on sheet 22
BOUT1_o: C292.2 R396.2 R398.1 U47.1(OUTA)
BOUT1_P: C294.2 ; also on sheet 22
BOUT1N: C297.1 R403.1
BOUT1P: C294.1 R400.1
BOUT2_a: C304.1 R410.1 R413.2 R414.1 R415.2
BOUT2_b: C304.2 R408.1 R409.2 R410.2 R411.2
BOUT2_c: C300.1 R413.1 U47.6(-INB)
BOUT2_d: C305.1 R411.1 U47.5(+INB)
BOUT2_e: C305.2 R405.2 R407.1 R408.2
BOUT2_N: C306.2 ; also on sheet 22
BOUT2_o: C300.2 R412.1 R414.2 U47.7(OUTB)
BOUT2_P: C302.2 ; also on sheet 22
BOUT2N: C306.1 R415.1
BOUT2P: C302.1 R409.1
BOUT3_a: C92.1 R164.1 R168.1 R169.2 R170.2
BOUT3_b: C92.2 R160.1 R162.2 R163.2 R164.2
BOUT3_c: C88.1 R169.1 U18.2(-INA)
BOUT3_d: C91.1 R163.1 U18.3(+INA)
BOUT3_e: C91.2 R153.2 R156.1 R160.2
BOUT3_N: C96.2 ; also on sheet 22
BOUT3_o: C88.2 R165.1 R168.2 U18.1(OUTA)
BOUT3_P: C90.2 ; also on sheet 22
BOUT3N: C96.1 R170.1
BOUT3P: C90.1 R162.1
BOUT4_a: C76.1 R140.1 R141.2 R149.1 R150.2
BOUT4_b: C76.2 R145.1 R147.2 R148.2 R149.2
BOUT4_c: C71.1 R141.1 U18.6(-INB)
BOUT4_d: C75.1 R148.1 U18.5(+INB)
BOUT4_e: C75.2 R139.2 R142.1 R145.2
BOUT4_N: C81.2 ; also on sheet 22
BOUT4_o: C71.2 R140.2 R143.1 U18.7(OUTB)
BOUT4_P: C73.2 ; also on sheet 22
BOUT4N: C81.1 R150.1
BOUT4P: C73.1 R147.1
BOUT5_a: C282.1 R369.2 R370.1 R377.1 R379.2
BOUT5_b: C282.2 R373.1 R375.2 R377.2 R378.2
BOUT5_c: C280.1 R369.1 U46.2(-INA)
BOUT5_d: C283.1 R378.1 U46.3(+INA)
BOUT5_e: C283.2 R368.2 R371.1 R373.2
BOUT5_N: C284.2 ; also on sheet 22
BOUT5_o: C280.2 R370.2 R372.1 U46.1(OUTA)
BOUT5_P: C281.2 ; also on sheet 22
BOUT5N: C284.1 R379.1
BOUT5P: C281.1 R375.1
BOUT6_a: C289.1 R387.1 R389.2 R390.1 R391.2
BOUT6_b: C289.2 R384.1 R385.2 R387.2 R388.2
BOUT6_c: C287.1 R389.1 U46.6(-INB)
BOUT6_d: C290.1 R388.1 U46.5(+INB)
BOUT6_e: C290.2 R381.2 R383.1 R384.2
BOUT6_N: C291.2 ; also on sheet 22
BOUT6_o: C287.2 R386.1 R390.2 U46.7(OUTB)
BOUT6_P: C288.2 ; also on sheet 22
BOUT6N: C291.1 R391.1
BOUT6P: C288.1 R385.1
BOUT7_a: C68.1 R135.1 R136.1 R137.2 R138.2
BOUT7_b: C68.2 R131.1 R132.2 R134.2 R135.2
BOUT7_c: C65.1 R137.1 U16.2(-INA)
BOUT7_d: C67.1 R134.1 U16.3(+INA)
BOUT7_e: C67.2 R127.2 R129.1 R131.2
BOUT7_N: C69.2 ; also on sheet 22
BOUT7_o: C65.2 R133.1 R136.2 U16.1(OUTA)
BOUT7_P: C66.2 ; also on sheet 22
BOUT7N: C69.1 R138.1
BOUT7P: C66.1 R132.1
BOUT8_a: C57.1 R106.1 R107.2 R115.1 R117.2
BOUT8_b: C57.2 R111.1 R113.2 R114.2 R115.2
BOUT8_c: C53.1 R107.1 U16.6(-INB)
BOUT8_d: C56.1 R114.1 U16.5(+INB)
BOUT8_e: C56.2 R105.2 R108.1 R111.2
BOUT8_N: C59.2 ; also on sheet 22
BOUT8_o: C53.2 R106.2 R109.1 U16.7(OUTB)
BOUT8_P: C55.2 ; also on sheet 22
BOUT8N: C59.1 R117.1
BOUT8P: C55.1 R113.1
CODECB_MIC2_L: J13.5A R430.1 R436.1
CODECB_MIC2_R: J13.2A R419.1 R427.1
CODECB_VOUT1: C293.2 J12.5B R404.1
CODECB_VOUT2: C301.2 J12.2B R406.1
CODECB_VOUT3: C89.2 J12.5A R155.1
CODECB_VOUT4: C72.2 J12.2A R151.1
CODECB_VOUT5: C279.2 J11.5B R380.1
CODECB_VOUT6: C286.2 J11.2B R382.1
CODECB_VOUT7: C64.2 J11.5A R128.1
CODECB_VOUT8: C52.2 J11.2A R118.1
MIC2BL_a: C319.2 R429.1 U50.1(OUTA)
MIC2BL_ac: C322.1 R435.1
MIC2BL_b: C319.1 R431.1 R435.2 U50.2(-INA)
MIC2BL_BIAS: C318.2 R430.2 R432.2
MIC2BL_BIAS_ac: C318.1 C321.1 R433.1 U49.6(-INB)
MIC2BL_c: C326.1 R439.1 R443.1 U50.6(-INB)
MIC2BL_d: C326.2 R444.1 U50.7(OUTB)
MIC2BL_PRE: C321.2 R433.2 R440.1 U49.7(OUTB)
MIC2BR_a: C307.2 R416.1 U48.1(OUTA)
MIC2BR_ac: C310.1 R423.1
MIC2BR_b: C307.1 R417.1 R423.2 U48.2(-INA)
MIC2BR_BIAS: C316.2 R425.2 R427.2
MIC2BR_BIAS_ac: C313.1 C316.1 R424.1 U49.2(-INA)
MIC2BR_c: C315.1 R422.1 R426.1 U48.6(-INB)
MIC2BR_d: C315.2 R428.1 U48.7(OUTB)
MIC2BR_PRE: C313.2 R418.1 R424.2 U49.1(OUTA)
VCOMAD2: C119.1 C309.1 C317.1 C769.1 C770.1 R425.1 R432.1 U48.3(+INA) U48.5(+INB) U49.3(+INA) U49.5(+INB) U50.3(+INA) U50.5(+INB) ; also on sheet 10 11 22
N24501627: C310.2 R419.2 R420.2
N24501939: R418.2 R420.1 R421.2
N24502423: R437.1 R438.2 R440.2
N24502429: C322.2 R436.2 R437.2
N24516386: C89.1 R165.2
N24516394: C293.1 R398.2
N24516779: C72.1 R143.2
N24516802: C301.1 R412.2
N24517434: C64.1 R133.2
N24517442: C279.1 R372.2
N24517839: C52.1 R109.2
N24517862: C286.1 R386.2

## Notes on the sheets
sheet 12
- CODEC-B STEREO MICROPHONE 2
- Single-Ended to Differential Buffer w/ Anti-Aliasing LPF
- "R1"
- BIAS
- PRE AMPLIFIER
- See Config
  Table
- To AUDIO
  CODEC-B VIN4
- Note: Full scale is 2Vrms  differentially
- "R3"
- Note: Gain = 1, f-3dB = 48kHz
- J13-TOP JACK
  MICIN L CODEC-B VIN3
  MICIN R CODEC-B VIN4
- See Config
  Table
- "R2"
- "R5"
- BIAS
- PRE AMPLIFIER
- Silkscreen:
  "CODEC-A MIC 1 & 2"
- To AUDIO
  CODEC-B VIN3
- Note: Full scale is 2Vrms  differentially
- "R6"
- Note: Gain = 1, f-3dB = 48kHz
- See Config
  Table
- "R4"
- Config Table
- Install
- Remove
- PASSIVE-MIC
- R2,R3,R5,R6
- R1,R4
- BIAS + PREAMP
- (default)
- ACTIVE-MIC
- BIAS ONLY
- R1,R2,R4,R5
- R3,R6
- LINE-INPUT
- NO BIAS/PREAMP
- R1,R4
- R2,R3,R5,R6
sheet 13
- CODEC-B STEREO LINE OUT
- Note: Full scale is 8Vpp differentially
- Note: Full scale is 8Vpp differentially
- Gain = 0.747; f–3 dB = 53 kHz
- Gain = 0.747; f–3 dB = 53 kHz
- J12-TOP JACK
  LOUT L CODEC-B VOUT3
  LOUT R CODEC-B VOUT4
- J12-BOTTOM JACK
  LOUT L CODEC-B VOUT1
  LOUT R CODEC-B VOUT2
- Silkscreen: "CODEC-B LINE OUT 3/4, 1/2"
- Note: Full scale is 8Vpp differentially
- Note: Full scale is 8Vpp differentially
- Gain = 0.747; f–3 dB = 53 kHz
- Gain = 0.747; f–3 dB = 53 kHz
- J11-TOP JACK
  LOUT L CODEC-B VOUT7
  LOUT R CODEC-B VOUT8
- J11-BOTTOM JACK
  LOUT L CODEC-B VOUT5
  LOUT R CODEC-B VOUT6
- Silkscreen: "CODEC-B LINE OUT 7/8, 5/6"
